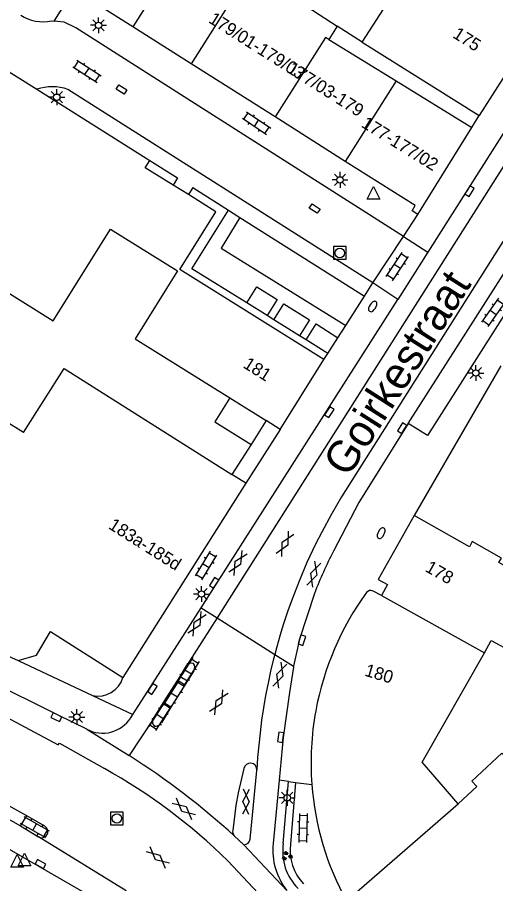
# Model space of a CAD drawing. Extents: x 132998 to 136004, y 396998 to 398512.
# Drawn here: x 133387.8 to 133425.6, y 397708.1 to 397776.5 of the extents above; entities that cross this region are included whole.
import ezdxf

# ---------------------------------------------------------------- set-up
doc = ezdxf.new("R2010")
doc.units = 0
for name, color, linetype in [('gg-afsc-erfafscheiding', 7, 'Continuous'), ('gg-afsc-muur', 7, 'Continuous'), ('gg-anno-huisnummerreeks BGT', 7, 'Continuous'), ('gg-anno-openbare ruimte label', 7, 'Continuous'), ('gg-bbg-gedigitaliseerde bebouwing', 7, 'Continuous'), ('gg-bbg-hoofdgebouw', 7, 'Continuous'), ('gg-bbg-luifel en loopbrug', 7, 'Continuous'), ('gg-bbg-tussenscheiding', 7, 'Continuous'), ('gg-knt-verharding', 7, 'Continuous'), ('gg-knt-verharding nz', 7, 'Continuous'), ('gt-grn-weggrens', 7, 'Continuous'), ('gt-symb-brandkraan', 7, 'Continuous'), ('gt-symb-gesloten verharding', 7, 'Continuous'), ('gt-symb-groenvak', 7, 'Continuous'), ('gt-symb-klinker verharding', 7, 'Continuous'), ('gt-symb-kolk', 7, 'Continuous'), ('gt-symb-kolk center center', 7, 'Continuous'), ('gt-symb-lichtmast', 7, 'Continuous'), ('gt-symb-rioolschacht', 7, 'Continuous'), ('gt-symb-waterafsluiter', 7, 'Continuous')]:
    doc.layers.add(name, color=color, linetype=linetype)

# ---------------------------------------------------------------- blocks, each defined once
blk = doc.blocks.new('gt0-KL1')
at = {"layer": 'gt-symb-klinker verharding'}
for p, q in [((-1.15, 0.3), (1.15, 0.3)), ((-1, -0.3), (-1, 0.3)), ((-0.5, 0.3), (-0.5, 0.45)), ((0, -0.3), (0, 0.3)), ((0.5, 0.3), (0.5, 0.45)), ((1, -0.3), (1, 0.3)), ((-1.15, -0.3), (1.15, -0.3)), ((-0.5, -0.45), (-0.5, -0.3)), ((0.5, -0.45), (0.5, -0.3))]:
    blk.add_line(p, q, dxfattribs=at)
blk = doc.blocks.new('gt0-LMAST')
at = {"layer": 'gt-symb-lichtmast'}
for p, q in [((-0.182, 0.173), (-0.447, 0.438)), ((-0.005, 0.246), (-0.005, 0.621)), ((0.172, 0.173), (0.437, 0.438)), ((-0.255, -0.004), (-0.63, -0.004)), ((-0.182, -0.181), (-0.447, -0.446)), ((-0.005, -0.254), (-0.005, -0.629)), ((0.437, -0.446), (0.172, -0.181)), ((0.245, -0.004), (0.62, -0.004))]:
    blk.add_line(p, q, dxfattribs=at)
blk.add_circle((-0.005, -0.004), 0.25, dxfattribs=at)
blk = doc.blocks.new('gt0-RS')
at = {"layer": 'gt-symb-rioolschacht'}
blk.add_lwpolyline([(-0.5, -0.5), (0.5, -0.5), (0.5, 0.5), (-0.5, 0.5)], close=True, dxfattribs=at)
blk.add_circle((0, 0), 0.375, dxfattribs=at)
blk = doc.blocks.new('gt0-KOLKCC')
at = {"layer": 'gt-symb-kolk center center'}
blk.add_lwpolyline([(-0.375, 0.2), (0.375, 0.2), (0.375, -0.2), (-0.375, -0.2)], close=True, dxfattribs=at)
blk = doc.blocks.new('gt0-WAFSL')
at = {"layer": 'gt-symb-waterafsluiter'}
for p, q in [((-0.5, -0.333), (0, 0.667)), ((0, 0.667), (0.5, -0.333)), ((0.5, -0.333), (-0.5, -0.333))]:
    blk.add_line(p, q, dxfattribs=at)
blk = doc.blocks.new('gt0-KOLK')
at = {"layer": 'gt-symb-kolk'}
blk.add_lwpolyline([(0, 0), (0.375, 0), (0.375, 0.4), (-0.375, 0.4), (-0.375, 0), (0, 0)], dxfattribs=at)
blk = doc.blocks.new('gt0-BR')
at = {"layer": 'gt-symb-brandkraan'}
for centre, radius, start, end in [((-0.244, 0), 0.206, 107.56694, 252.43307), ((0.599, -2.664), 3, 106.89205, 107.56694), ((0, -0.691), 0.938, 73.10799, 106.89205), ((-0.599, -2.664), 3, 72.43309, 73.10799), ((0.244, 0), 0.206, 287.56695, 72.43309), ((0.599, 2.664), 3, 252.43307, 253.10797), ((0, 0.691), 0.938, 253.10797, 286.89206), ((-0.599, 2.664), 3, 286.89206, 287.56695)]:
    blk.add_arc(centre, radius, start, end, dxfattribs=at)
blk = doc.blocks.new('gt0-GESVH1')
at = {"layer": 'gt-symb-gesloten verharding'}
for p, q in [((-0.992, -0.261), (0.008, 0.239)), ((0.008, -0.261), (-0.992, 0.239)), ((0.008, 0.239), (1.008, -0.261)), ((1.008, 0.239), (0.008, -0.261))]:
    blk.add_line(p, q, dxfattribs=at)
blk = doc.blocks.new('gt0-GRVAK')
at = {"layer": 'gt-symb-groenvak'}
for p, q in [((-0.11, 0.189), (-0.228, 0.24)), ((-0.182, 0.153), (0.088, 0.153)), ((-0.091, 0.211), (-0.156, 0.322)), ((-0.047, 0.214), (-0.047, 0.393)), ((-0.004, 0.211), (0.061, 0.322)), ((0.015, 0.189), (0.133, 0.24)), ((0.262, -0.052), (0.197, 0.059)), ((0.305, -0.049), (0.305, 0.13)), ((0.349, -0.052), (0.414, 0.059)), ((-0.245, -0.228), (-0.363, -0.177)), ((-0.318, -0.264), (-0.047, -0.264)), ((-0.226, -0.206), (-0.291, -0.095)), ((-0.183, -0.203), (-0.183, -0.024)), ((-0.139, -0.206), (-0.074, -0.095)), ((-0.12, -0.228), (-0.002, -0.177)), ((0.243, -0.074), (0.125, -0.023)), ((0.17, -0.11), (0.441, -0.11)), ((0.368, -0.074), (0.486, -0.023))]:
    blk.add_line(p, q, dxfattribs=at)

msp = doc.modelspace()

# ---------------------------------------------------------------- linework, layer by layer
at = {"layer": 'gg-afsc-erfafscheiding'}
for p, q in [((133415.07, 397774.567), (133413.108, 397775.823)), ((133426.02, 397748.98), (133419.19, 397737.15)), ((133406.302, 397742.768), (133404.781, 397740.395))]:
    msp.add_line(p, q, dxfattribs=at)
at = {"layer": 'gg-afsc-muur'}
msp.add_line((133387.9, 397725.69), (133393.78, 397722.929), dxfattribs=at)
msp.add_arc((133394.214, 397724.929), 2.046, 257.75057, 343.86045, dxfattribs=at)
at = {"layer": 'gg-bbg-gedigitaliseerde bebouwing'}
for p, q in [((133415.07, 397774.567), (133419.398, 397781.308)), ((133410.697, 397777.369), (133413.108, 397775.823)), ((133413.108, 397775.823), (133412.442, 397774.769)), ((133412.442, 397774.769), (133417.756, 397771.488)), ((133415.07, 397774.567), (133424.32, 397768.75)), ((133417.756, 397771.488), (133423.73, 397767.8)), ((133404.634, 397746.446), (133407.508, 397744.65)), ((133419.808, 397717.67), (133424.735, 397726.313)), ((133422.669, 397714.374), (133419.808, 397717.67))]:
    msp.add_line(p, q, dxfattribs=at)
for points in [[(133373.642, 397763.628), (133373.451, 397763.322), (133390.68, 397752.542), (133395.208, 397759.78), (133400.491, 397756.475), (133397.145, 397751.126), (133404.634, 397746.446)], [(133388.322, 397743.704), (133391.544, 397748.77), (133404.781, 397740.395)], [(133388.322, 397743.704), (133386.942, 397744.581), (133385.14, 397741.746), (133386.519, 397740.869)], [(133431.06, 397730.545), (133431.275, 397730.913), (133429.189, 397732.085), (133428.961, 397731.691), (133425.871, 397733.429), (133426.088, 397733.793), (133423.775, 397735.091), (133423.55, 397734.69), (133419.19, 397737.15)], [(133424.735, 397726.313), (133425.28, 397727.268), (133441.25, 397718.657)], [(133422.669, 397714.374), (133424.135, 397715.75), (133423.749, 397716.161), (133426.103, 397718.37), (133428.312, 397716.017), (133429.242, 397716.824), (133430.071, 397715.869), (133429.826, 397715.656), (133432.915, 397712.098)]]:
    msp.add_lwpolyline(points, dxfattribs=at)
at = {"layer": 'gg-bbg-hoofdgebouw'}
for p, q in [((133396.953, 397775.766), (133392.32, 397778.7)), ((133429.58, 397777.03), (133424.32, 397768.75)), ((133381.462, 397775.826), (133389.388, 397770.831)), ((133401.571, 397772.842), (133396.953, 397775.766)), ((133408.195, 397768.647), (133401.571, 397772.842)), ((133389.388, 397770.831), (133398.307, 397765.21)), ((133413.735, 397765.139), (133408.195, 397768.647)), ((133419.48, 397760.93), (133423.73, 397767.8)), ((133401.35, 397762.51), (133400.148, 397763.261)), ((133408.61, 397743.96), (133412.06, 397749.47)), ((133408.61, 397743.96), (133407.508, 397744.65)), ((133405.88, 397739.7), (133404.781, 397740.395)), ((133405.88, 397739.7), (133396.18, 397724.36)), ((133416.6, 397730.84), (133415.939, 397731.18)), ((133376.74, 397730.83), (133387.9, 397725.69))]:
    msp.add_line(p, q, dxfattribs=at)
for points in [[(133400.148, 397763.261), (133397.948, 397764.635), (133398.307, 397765.21)], [(133419.48, 397760.93), (133419.03, 397761.23), (133419.26, 397761.64), (133413.735, 397765.139)], [(133412.06, 397749.47), (133400.681, 397756.585), (133403.531, 397761.148), (133401.35, 397762.51)], [(133419.19, 397737.15), (133416.35, 397732.11), (133417.08, 397731.69), (133416.6, 397730.84)], [(133387.9, 397725.69), (133389.36, 397726.11), (133390.45, 397727.99), (133396.18, 397724.36)]]:
    msp.add_lwpolyline(points, dxfattribs=at)
for centre, radius, start, end in [((133415.747, 397730.834), 0.396, 60.9911, 145.5146), ((133433.836, 397717.624), 22.794, 143.88854, 169.67138), ((133433.859, 397717.622), 22.818, 169.67571, 184.30701), ((133433.84, 397717.626), 22.799, 184.32265, 208.63692)]:
    msp.add_arc(centre, radius, start, end, dxfattribs=at)
at = {"layer": 'gg-bbg-luifel en loopbrug'}
msp.add_line((133407.508, 397744.65), (133406.302, 397742.768), dxfattribs=at)
msp.add_lwpolyline([(133404.634, 397746.446), (133403.451, 397744.552), (133406.302, 397742.768)], dxfattribs=at)
at = {"layer": 'gg-bbg-tussenscheiding'}
for p, q in [((133401.606, 397783.113), (133396.953, 397775.766)), ((133406.225, 397780.192), (133401.571, 397772.842)), ((133417.756, 397771.488), (133413.735, 397765.139)), ((133416.6, 397730.84), (133424.735, 397726.313)), ((133413.83, 397706.7), (133422.669, 397714.374))]:
    msp.add_line(p, q, dxfattribs=at)
msp.add_lwpolyline([(133412.442, 397774.769), (133412.176, 397774.933), (133408.195, 397768.647)], dxfattribs=at)
at = {"layer": 'gg-knt-verharding'}
for p, q in [((133390.75, 397776.217), (133392.32, 397778.7)), ((133390.528, 397776.239), (133390.75, 397776.217)), ((133415.92, 397755.53), (133391.839, 397770.82)), ((133398.307, 397765.21), (133400.5, 397763.825)), ((133400.5, 397763.825), (133400.148, 397763.261)), ((133401.698, 397763.068), (133401.35, 397762.51)), ((133401.698, 397763.068), (133404.508, 397761.292)), ((133418.719, 397744.435), (133429.797, 397761.838)), ((133405.427, 397760.712), (133415.262, 397754.498)), ((133418.35, 397759.21), (133419.48, 397760.93)), ((133415.92, 397755.53), (133418.35, 397759.21)), ((133420.253, 397757.953), (133417.892, 397754.228)), ((133415.262, 397754.498), (133415.92, 397755.53)), ((133413.783, 397752.175), (133415.262, 397754.498)), ((133402.363, 397729.871), (133417.892, 397754.228)), ((133407.575, 397752.948), (133405.972, 397753.947)), ((133408.1, 397752.621), (133407.575, 397752.948)), ((133410.131, 397751.356), (133408.1, 397752.621)), ((133410.654, 397751.03), (133410.131, 397751.356)), ((133412.372, 397749.96), (133410.654, 397751.03)), ((133412.372, 397749.96), (133413.156, 397751.191)), ((133412.06, 397749.47), (133412.372, 397749.96)), ((133408.61, 397743.96), (133405.88, 397739.7)), ((133411.312, 397731.001), (133410.129, 397727.373)), ((133402.363, 397729.871), (133403.621, 397729.073)), ((133403.621, 397729.073), (133408.176, 397726.182)), ((133410.129, 397727.373), (133409.662, 397725.239)), ((133408.176, 397726.182), (133409.662, 397725.239)), ((133400.708, 397724.442), (133401.215, 397725.274)), ((133399.399, 397722.366), (133400.708, 397724.442)), ((133400.708, 397724.442), (133401.295, 397724.101)), ((133401.787, 397724.892), (133401.295, 397724.101)), ((133401.295, 397724.101), (133399.968, 397721.999)), ((133398.567, 397721.071), (133399.399, 397722.366)), ((133399.968, 397721.999), (133399.399, 397722.366)), ((133399.968, 397721.999), (133399.216, 397720.768)), ((133396.799, 397721.172), (133396.968, 397721.432)), ((133408.523, 397716.229), (133408.043, 397711.225)), ((133408.848, 397711.246), (133409.251, 397716.139)), ((133409.251, 397716.139), (133409.822, 397716.068)), ((133409.822, 397716.068), (133409.415, 397711.178)), ((133388.583, 397713.423), (133385.058, 397715.396)), ((133384.587, 397714.576), (133388.094, 397712.634)), ((133388.094, 397712.634), (133388.583, 397713.423)), ((133390.002, 397712.614), (133388.583, 397713.423)), ((133388.094, 397712.634), (133389.522, 397711.76))]:
    msp.add_line(p, q, dxfattribs=at)
for points in [[(133458.53, 397817.701), (133444.514, 397796.082), (133433.077, 397778.183), (133420.253, 397757.953)], [(133418.35, 397759.21), (133392.45, 397775.69), (133391.54, 397776.14), (133390.75, 397776.217)], [(133405.972, 397753.947), (133401.629, 397756.653), (133404.508, 397761.292)], [(133429.797, 397761.838), (133431.298, 397760.856), (133420.241, 397743.47), (133418.719, 397744.435)], [(133405.427, 397760.712), (133403.954, 397758.28), (133413.783, 397752.175)], [(133405.972, 397753.947), (133406.764, 397755.22), (133408.37, 397754.224), (133407.575, 397752.948)], [(133408.1, 397752.621), (133408.881, 397753.89), (133410.92, 397752.623), (133410.131, 397751.356)], [(133410.654, 397751.03), (133411.434, 397752.29), (133413.156, 397751.191)], [(133418.719, 397744.435), (133414.825, 397738.191), (133412.81, 397734.331)], [(133396.968, 397721.432), (133398.346, 397723.553), (133402.363, 397729.871)], [(133393.328, 397720.267), (133391.011, 397721.392), (133385.55, 397724.108), (133383.222, 397725.214)], [(133409.662, 397725.239), (133409.649, 397725.182), (133409.346, 397723.173), (133408.847, 397719.601), (133408.523, 397716.229)], [(133378.598, 397715.634), (133386.7, 397711.092), (133394.052, 397706.834)]]:
    msp.add_lwpolyline(points, dxfattribs=at)
for centre, radius, start, end in [((133389.856, 397779.306), 3.14, 236.43014, 282.35353), ((133390.597, 397767.256), 3.774, 70.79639, 108.68933), ((133441.049, 397719.626), 31.838, 152.49203, 159.06678), ((133401.645, 397724.936), 0.547, 79.14728, 141.79979), ((133401.368, 397725.156), 0.495, 327.82057, 39.85994), ((133394.571, 397722.608), 2.651, 242.03407, 327.1929), ((133398.976, 397720.855), 0.463, 152.13488, 225.87468), ((133398.762, 397721.039), 0.529, 258.17477, 329.10537), ((133389.764, 397712.186), 0.49, 240.34361, 60.97911), ((133413.158, 397710.717), 5.14, 174.32861, 218.38674), ((133412.938, 397710.619), 4.138, 171.28208, 225.09435), ((133413.189, 397710.7), 3.804, 172.77838, 223.88171)]:
    msp.add_arc(centre, radius, start, end, dxfattribs=at)
at = {"layer": 'gg-knt-verharding nz'}
for p, q in [((133404.57, 397730.571), (133403.621, 397729.073)), ((133403.621, 397729.073), (133401.215, 397725.274)), ((133398.567, 397721.071), (133396.674, 397718.179)), ((133396.44, 397707.499), (133389.522, 397711.76)), ((133405.723, 397711.145), (133404.979, 397711.855))]:
    msp.add_line(p, q, dxfattribs=at)
for points in [[(133461.811, 397820.264), (133437.871, 397783.148), (133404.57, 397730.571)], [(133464.442, 397818.455), (133464.387, 397818.37), (133450.239, 397796.519), (133441.226, 397782.471), (133430.38, 397765.411), (133413.458, 397738.641), (133412.646, 397737.259), (133411.882, 397735.849), (133411.401, 397734.895), (133410.72, 397733.443), (133410.091, 397731.969), (133409.54, 397730.548), (133409.208, 397729.616), (133408.896, 397728.678), (133408.74, 397728.173)], [(133408.74, 397728.173), (133408.604, 397727.733), (133408.333, 397726.782), (133408.176, 397726.182)], [(133408.176, 397726.182), (133408.082, 397725.825), (133407.851, 397724.863), (133407.641, 397723.897), (133407.452, 397722.926), (133407.284, 397721.951), (133407.137, 397720.973), (133407.01, 397719.992), (133406.905, 397719.009), (133406.821, 397718.023), (133406.76, 397717.06)], [(133385.404, 397722.031), (133386.603, 397721.44), (133391.068, 397719.024), (133391.167, 397719.169), (133394.73, 397717.155)], [(133405.735, 397717.163), (133405.292, 397715.233), (133405.09, 397714.243), (133404.856, 397712.258)], [(133406.243, 397711.59), (133406.756, 397717.014), (133406.76, 397717.06)], [(133404.469, 397709.866), (133410.43, 397703.508), (133410.909, 397702.981)]]:
    msp.add_lwpolyline(points, dxfattribs=at)
for centre, radius, start, end in [((133363.403, 397665.871), 61.992, 47.88222, 57.54149), ((133406.244, 397717.076), 0.516, 358.18672, 170.33675), ((133372.696, 397677.564), 45.309, 45.47288, 60.90225), ((133405.294, 397712.171), 0.447, 168.8204, 225.12512), ((133405.714, 397711.682), 0.537, 270.99994, 350.11184)]:
    msp.add_arc(centre, radius, start, end, dxfattribs=at)
at = {"layer": 'gt-grn-weggrens'}
for p, q in [((133423.73, 397767.8), (133424.32, 397768.75)), ((133404.508, 397761.292), (133405.427, 397760.712)), ((133418.35, 397759.21), (133420.253, 397757.953)), ((133417.892, 397754.228), (133415.92, 397755.53)), ((133413.156, 397751.191), (133413.783, 397752.175)), ((133393.78, 397722.929), (133396.968, 397721.432)), ((133393.328, 397720.267), (133396.674, 397718.179)), ((133409.251, 397716.139), (133408.523, 397716.229)), ((133409.822, 397716.068), (133411.106, 397715.908)), ((133405.723, 397711.145), (133409.129, 397707.525))]:
    msp.add_line(p, q, dxfattribs=at)

# ---------------------------------------------------------------- block references
at = {"layer": 'gt-symb-brandkraan'}
for p, rotation in [((133415.911, 397753.671), -122.29094835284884), ((133416.579, 397735.761), -117.86077183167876)]:
    msp.add_blockref('gt0-BR', p, dxfattribs=dict(at, rotation=rotation))
at = {"layer": 'gt-symb-gesloten verharding'}
for p, rotation in [((133408.995, 397734.924), -118.28136108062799), ((133405.279, 397733.41), -121.13079914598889), ((133411.265, 397732.516), -108.18126897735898), ((133402.045, 397728.594), -121.13079914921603), ((133408.582, 397724.534), -108.18126897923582), ((133403.765, 397722.401), -121.13079914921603), ((133405.911, 397714.555), -91.89196541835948), ((133401.003, 397713.981), -41.024134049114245), ((133398.931, 397710.152), -41.02413405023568)]:
    msp.add_blockref('gt0-GESVH1', p, dxfattribs=dict(at, rotation=rotation))
at = {"layer": 'gt-symb-groenvak'}
msp.add_blockref('gt0-GRVAK', (133409.127, 397710.244), dxfattribs=at)
at = {"layer": 'gt-symb-klinker verharding'}
for p, rotation in [((133393.345, 397772.252), -32.46679945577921), ((133406.735, 397768.151), -34.07160980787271), ((133417.852, 397756.824), 56.54839854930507), ((133425.421, 397753.203), -125.23135738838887), ((133402.733, 397733.204), -121.13079914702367), ((133401.335, 397724.8), -122.54589339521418), ((133400.23, 397722.986), -122.54589339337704), ((133399.108, 397721.287), -122.54589339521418), ((133389.209, 397712.531), -29.46071361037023), ((133410.405, 397712.46), -91.20303454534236)]:
    msp.add_blockref('gt0-KL1', p, dxfattribs=dict(at, rotation=rotation))
at = {"layer": 'gt-symb-kolk'}
for p, rotation in [((133423.387, 397762.899), -122.4184499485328), ((133412.318, 397745.436), -122.54589339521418), ((133418.401, 397743.95), 58.122183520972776), ((133403.546, 397731.732), 57.556658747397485), ((133410.129, 397727.373), -108.05980476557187), ((133398.346, 397723.553), -123.0208227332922), ((133391.011, 397721.392), 153.56486281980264), ((133408.847, 397719.601), 82.04221697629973), ((133389.573, 397709.437), -29.945075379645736)]:
    msp.add_blockref('gt0-KOLK', p, dxfattribs=dict(at, rotation=rotation))
at = {"layer": 'gt-symb-kolk center center'}
for p, rotation in [((133396.075, 397770.816), -32.4667994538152), ((133411.328, 397761.402), -32.46679945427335)]:
    msp.add_blockref('gt0-KOLKCC', p, dxfattribs=dict(at, rotation=rotation))
at = {"layer": 'gt-symb-lichtmast', "rotation": 90}
for p in [(133394.25, 397775.896), (133413.328, 397763.679)]:
    msp.add_blockref('gt0-LMAST', p, dxfattribs=at)
at = {"layer": 'gt-symb-lichtmast'}
for p in [(133390.965, 397770.211), (133424.057, 397748.418), (133402.393, 397730.95), (133392.548, 397721.235), (133409.162, 397714.85)]:
    msp.add_blockref('gt0-LMAST', p, dxfattribs=at)
at = {"layer": 'gt-symb-rioolschacht'}
for p in [(133413.305, 397757.897), (133395.709, 397713.215)]:
    msp.add_blockref('gt0-RS', p, dxfattribs=at)
at = {"layer": 'gt-symb-waterafsluiter'}
for p in [(133415.967, 397762.494), (133387.83, 397709.704), (133388.418, 397709.806)]:
    msp.add_blockref('gt0-WAFSL', p, dxfattribs=at)

# ---------------------------------------------------------------- texts
at = {"layer": 'gg-anno-huisnummerreeks BGT'}
for s, rotation, p in [('179/01-179/03', 327.7, (133402.877, 397776.154)), ('175', 327.6, (133422.154, 397774.972)), ('177/03-179', 327.7, (133409.074, 397772.23)), ('177-177/02', 328.2, (133414.935, 397767.905)), ('181', 327.9, (133405.603, 397748.889)), ('183a-185d', 327.7, (133394.966, 397736.172)), ('178', 330.6, (133419.983, 397732.782)), ('180', 343.2, (133415.214, 397724.508))]:
    msp.add_text(s, height=1, rotation=rotation, dxfattribs=at).set_placement(p)
at = {"layer": 'gg-anno-openbare ruimte label'}
msp.add_text('Goirkestraat', height=2.5, rotation=57.5, dxfattribs=at).set_placement((133413.97, 397740.083))

doc.saveas('drawing.dxf')
